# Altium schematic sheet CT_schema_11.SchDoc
size 389 x 278 mm
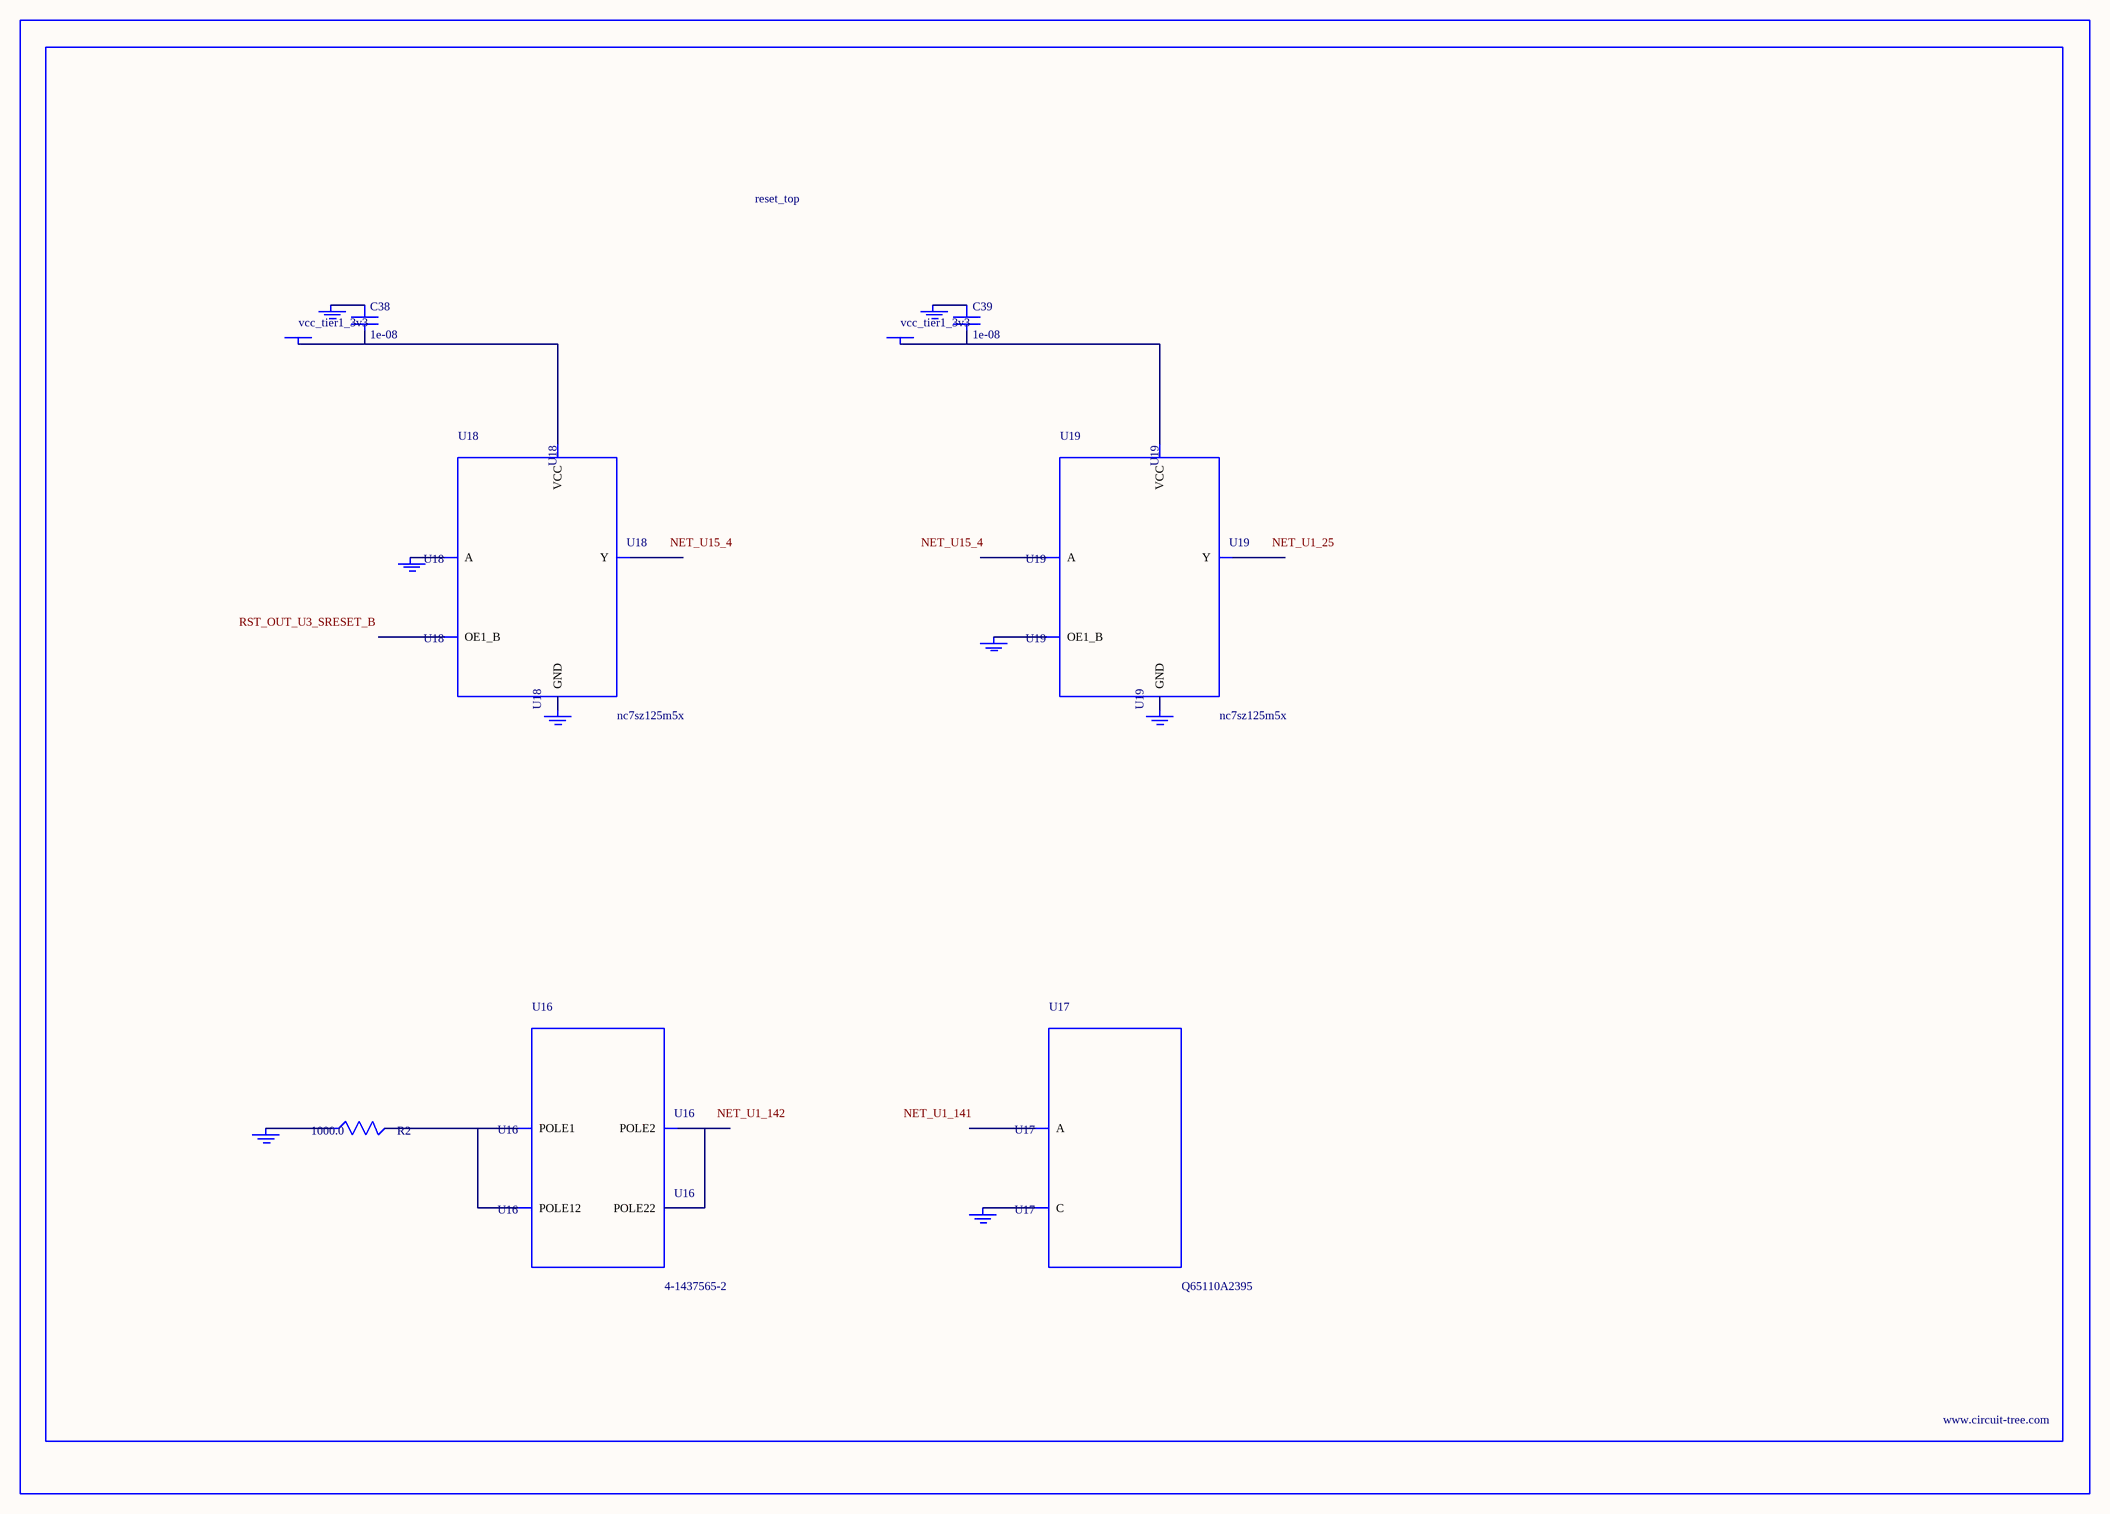
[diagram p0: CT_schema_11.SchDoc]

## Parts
BORDER10  (no value)
C38  1e-08  [C0402]
C39  1e-08  [C0402]
GND_INSTANCE_10_0  (no value)
GND_INSTANCE_10_1  (no value)
GND_INSTANCE_10_2  (no value)
GND_INSTANCE_10_3  (no value)
GND_INSTANCE_10_4  (no value)
GND_INSTANCE_10_5  (no value)
GND_INSTANCE_10_6  (no value)
GND_INSTANCE_10_7  (no value)
POWER_INSTANCE_10_0  vcc_tier1_3v3
POWER_INSTANCE_10_1  vcc_tier1_3v3
R2  1000.0  [R0603]
U16  4-1437565-2  [SW_4-1437565-2]
U17  Q65110A2395  [LGM67K-G1J2-24-Z]
U18  nc7sz125m5x  [NC7SZ125M5X]
U19  nc7sz125m5x  [NC7SZ125M5X]

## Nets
NetC38_1: C38.1 GND_INSTANCE_10_2.0(GND)
NetC38_2: C38.2 POWER_INSTANCE_10_0.0(PWR) U18.5(VCC)
NetC39_1: C39.1 GND_INSTANCE_10_5.0(GND)
NetC39_2: C39.2 POWER_INSTANCE_10_1.0(PWR) U19.5(VCC)
NetGND_INSTANCE_10_0_0: GND_INSTANCE_10_0.0(GND) R2.1
NetGND_INSTANCE_10_1_0: GND_INSTANCE_10_1.0(GND) U17.C
NetGND_INSTANCE_10_3_0: GND_INSTANCE_10_3.0(GND) U18.2(A)
NetGND_INSTANCE_10_4_0: GND_INSTANCE_10_4.0(GND) U18.3(GND)
NetGND_INSTANCE_10_6_0: GND_INSTANCE_10_6.0(GND) U19.1(OE1_B)
NetGND_INSTANCE_10_7_0: GND_INSTANCE_10_7.0(GND) U19.3(GND)
NetR2_2: R2.2 U16.1(POLE1) U16.2(POLE12)
NetU16_3: U16.3(POLE2) U16.4(POLE22)

Not connected (* = marked no-connect by the designer): U17 A; U18 1(OE1_B) 4(Y); U19 2(A) 4(Y)

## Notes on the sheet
- Labels drawn without touching a wire or pin: NET_U1_25, NET_U1_141, NET_U1_142, NET_U15_4, RST_OUT_U3_SRESET_B

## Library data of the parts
BORDER10 = BORDER_PAGE10
C38 C39 = C0402C103K3RAC
GND_INSTANCE_10_0-GND_INSTANCE_10_7 = GND
POWER_INSTANCE_10_0 POWER_INSTANCE_10_1 = PWR
R2 = RC0603JR-071KL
